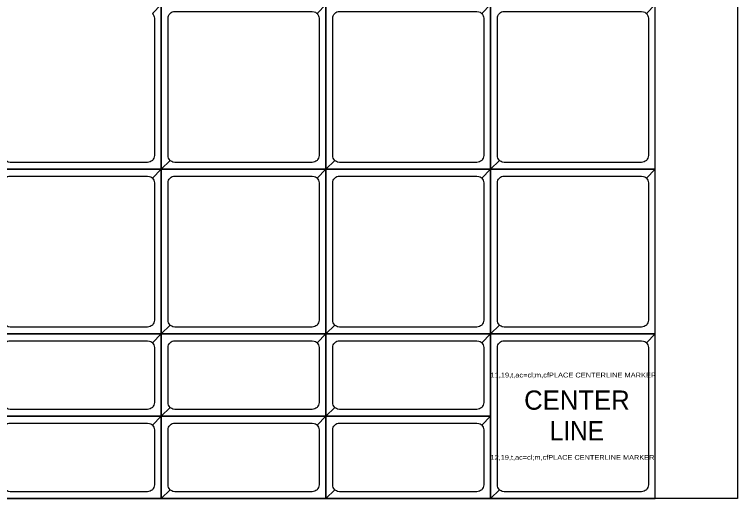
# Model space of a CAD drawing. Extents: x 67896 to 67908, y 49158.5 to 49162.6.
# Drawn here: x 67905.354 to 67907.989, y 49159.033 to 49160.797 of the extents above; entities that cross this region are included whole.
import ezdxf
from ezdxf.enums import TextEntityAlignment as Align

# ---------------------------------------------------------------- set-up
doc = ezdxf.new("R2010")
doc.units = 0
doc.header["$LTSCALE"] = 0.02
for name, color, linetype, lineweight in [('1', 7, 'Continuous', 25), ('2', 7, 'Continuous', 25), ('3', 7, 'Continuous', 25), ('4', 7, 'Continuous', 25), ('5', 7, 'Continuous', 25)]:
    doc.layers.add(name, color=color, linetype=linetype, lineweight=lineweight)
doc.layers.add('63', color=7, linetype='Continuous')

msp = doc.modelspace()

# ---------------------------------------------------------------- linework, layer by layer
at = {"layer": '1'}
for points in [[(67905.2889, 49160.2331), (67905.8889, 49160.2331), (67905.8889, 49160.8331), (67905.2889, 49160.8331)], [(67905.8889, 49160.2331), (67906.4889, 49160.2331), (67906.4889, 49160.8331), (67905.8889, 49160.8331)], [(67906.4889, 49160.2331), (67907.0889, 49160.2331), (67907.0889, 49160.8331), (67906.4889, 49160.8331)], [(67907.0889, 49160.2331), (67907.6889, 49160.2331), (67907.6889, 49160.8331), (67907.0889, 49160.8331)], [(67905.2889, 49159.6331), (67905.8889, 49159.6331), (67905.8889, 49160.2331), (67905.2889, 49160.2331)], [(67905.8889, 49159.6331), (67906.4889, 49159.6331), (67906.4889, 49160.2331), (67905.8889, 49160.2331)], [(67906.4889, 49159.6331), (67907.0889, 49159.6331), (67907.0889, 49160.2331), (67906.4889, 49160.2331)], [(67907.0889, 49159.6331), (67907.6889, 49159.6331), (67907.6889, 49160.2331), (67907.0889, 49160.2331)], [(67905.2889, 49159.3331), (67905.8889, 49159.3331), (67905.8889, 49159.6331), (67905.2889, 49159.6331)], [(67905.8889, 49159.3331), (67906.4889, 49159.3331), (67906.4889, 49159.6331), (67905.8889, 49159.6331)], [(67906.4889, 49159.3331), (67907.0889, 49159.3331), (67907.0889, 49159.6331), (67906.4889, 49159.6331)], [(67907.0889, 49159.0331), (67907.6889, 49159.0331), (67907.6889, 49159.6331), (67907.0889, 49159.6331)], [(67905.2889, 49159.0331), (67905.8889, 49159.0331), (67905.8889, 49159.3331), (67905.2889, 49159.3331)], [(67905.8889, 49159.0331), (67906.4889, 49159.0331), (67906.4889, 49159.3331), (67905.8889, 49159.3331)], [(67906.4889, 49159.0331), (67907.0889, 49159.0331), (67907.0889, 49159.3331), (67906.4889, 49159.3331)]]:
    msp.add_lwpolyline(points, close=True, dxfattribs=at)
at = {"layer": '2'}
for points in [[(67907.9889, 49159.0331), (67895.9889, 49159.0331), (67895.9889, 49162.6331), (67907.9889, 49162.6331)], [(67905.2889, 49160.2331), (67905.8889, 49160.2331), (67905.8889, 49160.8331), (67905.2889, 49160.8331)], [(67905.8889, 49160.2331), (67906.4889, 49160.2331), (67906.4889, 49160.8331), (67905.8889, 49160.8331)], [(67906.4889, 49160.2331), (67907.0889, 49160.2331), (67907.0889, 49160.8331), (67906.4889, 49160.8331)], [(67907.0889, 49160.2331), (67907.6889, 49160.2331), (67907.6889, 49160.8331), (67907.0889, 49160.8331)], [(67905.2889, 49159.6331), (67905.8889, 49159.6331), (67905.8889, 49160.2331), (67905.2889, 49160.2331)], [(67905.8889, 49159.6331), (67906.4889, 49159.6331), (67906.4889, 49160.2331), (67905.8889, 49160.2331)], [(67906.4889, 49159.6331), (67907.0889, 49159.6331), (67907.0889, 49160.2331), (67906.4889, 49160.2331)], [(67907.0889, 49159.6331), (67907.6889, 49159.6331), (67907.6889, 49160.2331), (67907.0889, 49160.2331)], [(67905.2889, 49159.3331), (67905.8889, 49159.3331), (67905.8889, 49159.6331), (67905.2889, 49159.6331)], [(67905.8889, 49159.3331), (67906.4889, 49159.3331), (67906.4889, 49159.6331), (67905.8889, 49159.6331)], [(67906.4889, 49159.3331), (67907.0889, 49159.3331), (67907.0889, 49159.6331), (67906.4889, 49159.6331)], [(67907.0889, 49159.0331), (67907.6889, 49159.0331), (67907.6889, 49159.6331), (67907.0889, 49159.6331)], [(67905.2889, 49159.0331), (67905.8889, 49159.0331), (67905.8889, 49159.3331), (67905.2889, 49159.3331)], [(67905.8889, 49159.0331), (67906.4889, 49159.0331), (67906.4889, 49159.3331), (67905.8889, 49159.3331)], [(67906.4889, 49159.0331), (67907.0889, 49159.0331), (67907.0889, 49159.3331), (67906.4889, 49159.3331)]]:
    msp.add_lwpolyline(points, close=True, dxfattribs=at)
at = {"layer": '3'}
for points in [[(67906.4889, 49160.8331), (67905.8889, 49160.8331), (67905.8889, 49160.2331), (67905.9212, 49160.2654), (67905.9181, 49160.2692), (67905.9158, 49160.2735), (67905.9144, 49160.2782), (67905.9139, 49160.2831), (67905.9139, 49160.7831), (67905.9144, 49160.788), (67905.9158, 49160.7927), (67905.9181, 49160.797), (67905.9212, 49160.8008), (67905.9212, 49160.8008), (67905.925, 49160.8039), (67905.9293, 49160.8062), (67905.934, 49160.8076), (67905.9389, 49160.8081), (67906.4389, 49160.8081), (67906.4462, 49160.807), (67906.4507, 49160.8051), (67906.4548, 49160.8024), (67906.4566, 49160.8008)], [(67907.0889, 49160.8331), (67906.4889, 49160.8331), (67906.4889, 49160.2331), (67906.5212, 49160.2654), (67906.5181, 49160.2692), (67906.5158, 49160.2735), (67906.5144, 49160.2782), (67906.5139, 49160.2831), (67906.5139, 49160.7831), (67906.5144, 49160.788), (67906.5158, 49160.7927), (67906.5181, 49160.797), (67906.5212, 49160.8008), (67906.5212, 49160.8008), (67906.525, 49160.8039), (67906.5293, 49160.8062), (67906.534, 49160.8076), (67906.5389, 49160.8081), (67907.0389, 49160.8081), (67907.0462, 49160.807), (67907.0507, 49160.8051), (67907.0548, 49160.8024), (67907.0566, 49160.8008)], [(67907.6889, 49160.8331), (67907.0889, 49160.8331), (67907.0889, 49160.2331), (67907.1212, 49160.2654), (67907.1181, 49160.2692), (67907.1158, 49160.2735), (67907.1144, 49160.2782), (67907.1139, 49160.2831), (67907.1139, 49160.7831), (67907.1144, 49160.788), (67907.1158, 49160.7927), (67907.1181, 49160.797), (67907.1212, 49160.8008), (67907.1212, 49160.8008), (67907.125, 49160.8039), (67907.1293, 49160.8062), (67907.134, 49160.8076), (67907.1389, 49160.8081), (67907.6389, 49160.8081), (67907.6462, 49160.807), (67907.6507, 49160.8051), (67907.6548, 49160.8024), (67907.6566, 49160.8008)], [(67905.8889, 49160.2331), (67905.2889, 49160.2331), (67905.2889, 49159.6331), (67905.3212, 49159.6654), (67905.3181, 49159.6692), (67905.3158, 49159.6735), (67905.3144, 49159.6782), (67905.3139, 49159.6831), (67905.3139, 49160.1831), (67905.3144, 49160.188), (67905.3158, 49160.1927), (67905.3181, 49160.197), (67905.3212, 49160.2008), (67905.3212, 49160.2008), (67905.325, 49160.2039), (67905.3293, 49160.2062), (67905.334, 49160.2076), (67905.3389, 49160.2081), (67905.8389, 49160.2081), (67905.8462, 49160.207), (67905.8507, 49160.2051), (67905.8548, 49160.2024), (67905.8566, 49160.2008)], [(67906.4889, 49160.2331), (67905.8889, 49160.2331), (67905.8889, 49159.6331), (67905.9212, 49159.6654), (67905.9181, 49159.6692), (67905.9158, 49159.6735), (67905.9144, 49159.6782), (67905.9139, 49159.6831), (67905.9139, 49160.1831), (67905.9144, 49160.188), (67905.9158, 49160.1927), (67905.9181, 49160.197), (67905.9212, 49160.2008), (67905.9212, 49160.2008), (67905.925, 49160.2039), (67905.9293, 49160.2062), (67905.934, 49160.2076), (67905.9389, 49160.2081), (67906.4389, 49160.2081), (67906.4462, 49160.207), (67906.4507, 49160.2051), (67906.4548, 49160.2024), (67906.4566, 49160.2008)], [(67907.0889, 49160.2331), (67906.4889, 49160.2331), (67906.4889, 49159.6331), (67906.5212, 49159.6654), (67906.5181, 49159.6692), (67906.5158, 49159.6735), (67906.5144, 49159.6782), (67906.5139, 49159.6831), (67906.5139, 49160.1831), (67906.5144, 49160.188), (67906.5158, 49160.1927), (67906.5181, 49160.197), (67906.5212, 49160.2008), (67906.5212, 49160.2008), (67906.525, 49160.2039), (67906.5293, 49160.2062), (67906.534, 49160.2076), (67906.5389, 49160.2081), (67907.0389, 49160.2081), (67907.0462, 49160.207), (67907.0507, 49160.2051), (67907.0548, 49160.2024), (67907.0566, 49160.2008)], [(67907.6889, 49160.2331), (67907.0889, 49160.2331), (67907.0889, 49159.6331), (67907.1212, 49159.6654), (67907.1181, 49159.6692), (67907.1158, 49159.6735), (67907.1144, 49159.6782), (67907.1139, 49159.6831), (67907.1139, 49160.1831), (67907.1144, 49160.188), (67907.1158, 49160.1927), (67907.1181, 49160.197), (67907.1212, 49160.2008), (67907.1212, 49160.2008), (67907.125, 49160.2039), (67907.1293, 49160.2062), (67907.134, 49160.2076), (67907.1389, 49160.2081), (67907.6389, 49160.2081), (67907.6462, 49160.207), (67907.6507, 49160.2051), (67907.6548, 49160.2024), (67907.6566, 49160.2008)], [(67905.8889, 49159.6331), (67905.2889, 49159.6331), (67905.2889, 49159.3331), (67905.3212, 49159.3654), (67905.3181, 49159.3692), (67905.3158, 49159.3735), (67905.3144, 49159.3782), (67905.3139, 49159.3831), (67905.3139, 49159.5831), (67905.3144, 49159.588), (67905.3158, 49159.5927), (67905.3181, 49159.597), (67905.3212, 49159.6008), (67905.3212, 49159.6008), (67905.325, 49159.6039), (67905.3293, 49159.6062), (67905.334, 49159.6076), (67905.3389, 49159.6081), (67905.8389, 49159.6081), (67905.8462, 49159.607), (67905.8507, 49159.6051), (67905.8548, 49159.6024), (67905.8566, 49159.6008)], [(67906.4889, 49159.6331), (67905.8889, 49159.6331), (67905.8889, 49159.3331), (67905.9212, 49159.3654), (67905.9181, 49159.3692), (67905.9158, 49159.3735), (67905.9144, 49159.3782), (67905.9139, 49159.3831), (67905.9139, 49159.5831), (67905.9144, 49159.588), (67905.9158, 49159.5927), (67905.9181, 49159.597), (67905.9212, 49159.6008), (67905.9212, 49159.6008), (67905.925, 49159.6039), (67905.9293, 49159.6062), (67905.934, 49159.6076), (67905.9389, 49159.6081), (67906.4389, 49159.6081), (67906.4462, 49159.607), (67906.4507, 49159.6051), (67906.4548, 49159.6024), (67906.4566, 49159.6008)], [(67907.0889, 49159.6331), (67906.4889, 49159.6331), (67906.4889, 49159.3331), (67906.5212, 49159.3654), (67906.5181, 49159.3692), (67906.5158, 49159.3735), (67906.5144, 49159.3782), (67906.5139, 49159.3831), (67906.5139, 49159.5831), (67906.5144, 49159.588), (67906.5158, 49159.5927), (67906.5181, 49159.597), (67906.5212, 49159.6008), (67906.5212, 49159.6008), (67906.525, 49159.6039), (67906.5293, 49159.6062), (67906.534, 49159.6076), (67906.5389, 49159.6081), (67907.0389, 49159.6081), (67907.0462, 49159.607), (67907.0507, 49159.6051), (67907.0548, 49159.6024), (67907.0566, 49159.6008)], [(67907.6889, 49159.6331), (67907.0889, 49159.6331), (67907.0889, 49159.0331), (67907.1212, 49159.0654), (67907.1181, 49159.0692), (67907.1158, 49159.0735), (67907.1144, 49159.0782), (67907.1139, 49159.0831), (67907.1139, 49159.5831), (67907.1144, 49159.588), (67907.1158, 49159.5927), (67907.1181, 49159.597), (67907.1212, 49159.6008), (67907.1212, 49159.6008), (67907.125, 49159.6039), (67907.1293, 49159.6062), (67907.134, 49159.6076), (67907.1389, 49159.6081), (67907.6389, 49159.6081), (67907.6462, 49159.607), (67907.6507, 49159.6051), (67907.6548, 49159.6024), (67907.6566, 49159.6008)], [(67905.8889, 49159.3331), (67905.2889, 49159.3331), (67905.2889, 49159.0331), (67905.3212, 49159.0654), (67905.3181, 49159.0692), (67905.3158, 49159.0735), (67905.3144, 49159.0782), (67905.3139, 49159.0831), (67905.3139, 49159.2831), (67905.3144, 49159.288), (67905.3158, 49159.2927), (67905.3181, 49159.297), (67905.3212, 49159.3008), (67905.3212, 49159.3008), (67905.325, 49159.3039), (67905.3293, 49159.3062), (67905.334, 49159.3076), (67905.3389, 49159.3081), (67905.8389, 49159.3081), (67905.8462, 49159.307), (67905.8507, 49159.3051), (67905.8548, 49159.3024), (67905.8566, 49159.3008)], [(67906.4889, 49159.3331), (67905.8889, 49159.3331), (67905.8889, 49159.0331), (67905.9212, 49159.0654), (67905.9181, 49159.0692), (67905.9158, 49159.0735), (67905.9144, 49159.0782), (67905.9139, 49159.0831), (67905.9139, 49159.2831), (67905.9144, 49159.288), (67905.9158, 49159.2927), (67905.9181, 49159.297), (67905.9212, 49159.3008), (67905.9212, 49159.3008), (67905.925, 49159.3039), (67905.9293, 49159.3062), (67905.934, 49159.3076), (67905.9389, 49159.3081), (67906.4389, 49159.3081), (67906.4462, 49159.307), (67906.4507, 49159.3051), (67906.4548, 49159.3024), (67906.4566, 49159.3008)], [(67907.0889, 49159.3331), (67906.4889, 49159.3331), (67906.4889, 49159.0331), (67906.5212, 49159.0654), (67906.5181, 49159.0692), (67906.5158, 49159.0735), (67906.5144, 49159.0782), (67906.5139, 49159.0831), (67906.5139, 49159.2831), (67906.5144, 49159.288), (67906.5158, 49159.2927), (67906.5181, 49159.297), (67906.5212, 49159.3008), (67906.5212, 49159.3008), (67906.525, 49159.3039), (67906.5293, 49159.3062), (67906.534, 49159.3076), (67906.5389, 49159.3081), (67907.0389, 49159.3081), (67907.0462, 49159.307), (67907.0507, 49159.3051), (67907.0548, 49159.3024), (67907.0566, 49159.3008)]]:
    msp.add_lwpolyline(points, close=True, dxfattribs=at)
at = {"layer": '4'}
for points in [[(67905.2889, 49160.2331), (67905.8889, 49160.2331), (67905.8889, 49160.8331), (67905.8566, 49160.8008), (67905.8597, 49160.797), (67905.862, 49160.7927), (67905.8634, 49160.788), (67905.8639, 49160.7831), (67905.8639, 49160.2831), (67905.8634, 49160.2782), (67905.862, 49160.2735), (67905.8597, 49160.2692), (67905.8566, 49160.2654), (67905.8566, 49160.2654), (67905.8528, 49160.2623), (67905.8485, 49160.26), (67905.8438, 49160.2586), (67905.8389, 49160.2581), (67905.3389, 49160.2581), (67905.3316, 49160.2592), (67905.3271, 49160.2611), (67905.323, 49160.2638), (67905.3212, 49160.2654)], [(67905.8889, 49160.2331), (67906.4889, 49160.2331), (67906.4889, 49160.8331), (67906.4566, 49160.8008), (67906.4597, 49160.797), (67906.462, 49160.7927), (67906.4634, 49160.788), (67906.4639, 49160.7831), (67906.4639, 49160.2831), (67906.4634, 49160.2782), (67906.462, 49160.2735), (67906.4597, 49160.2692), (67906.4566, 49160.2654), (67906.4566, 49160.2654), (67906.4528, 49160.2623), (67906.4485, 49160.26), (67906.4438, 49160.2586), (67906.4389, 49160.2581), (67905.9389, 49160.2581), (67905.9316, 49160.2592), (67905.9271, 49160.2611), (67905.923, 49160.2638), (67905.9212, 49160.2654)], [(67906.4889, 49160.2331), (67907.0889, 49160.2331), (67907.0889, 49160.8331), (67907.0566, 49160.8008), (67907.0597, 49160.797), (67907.062, 49160.7927), (67907.0634, 49160.788), (67907.0639, 49160.7831), (67907.0639, 49160.2831), (67907.0634, 49160.2782), (67907.062, 49160.2735), (67907.0597, 49160.2692), (67907.0566, 49160.2654), (67907.0566, 49160.2654), (67907.0528, 49160.2623), (67907.0485, 49160.26), (67907.0438, 49160.2586), (67907.0389, 49160.2581), (67906.5389, 49160.2581), (67906.5316, 49160.2592), (67906.5271, 49160.2611), (67906.523, 49160.2638), (67906.5212, 49160.2654)], [(67907.0889, 49160.2331), (67907.6889, 49160.2331), (67907.6889, 49160.8331), (67907.6566, 49160.8008), (67907.6597, 49160.797), (67907.662, 49160.7927), (67907.6634, 49160.788), (67907.6639, 49160.7831), (67907.6639, 49160.2831), (67907.6634, 49160.2782), (67907.662, 49160.2735), (67907.6597, 49160.2692), (67907.6566, 49160.2654), (67907.6566, 49160.2654), (67907.6528, 49160.2623), (67907.6485, 49160.26), (67907.6438, 49160.2586), (67907.6389, 49160.2581), (67907.1389, 49160.2581), (67907.1316, 49160.2592), (67907.1271, 49160.2611), (67907.123, 49160.2638), (67907.1212, 49160.2654)], [(67905.2889, 49159.6331), (67905.8889, 49159.6331), (67905.8889, 49160.2331), (67905.8566, 49160.2008), (67905.8597, 49160.197), (67905.862, 49160.1927), (67905.8634, 49160.188), (67905.8639, 49160.1831), (67905.8639, 49159.6831), (67905.8634, 49159.6782), (67905.862, 49159.6735), (67905.8597, 49159.6692), (67905.8566, 49159.6654), (67905.8566, 49159.6654), (67905.8528, 49159.6623), (67905.8485, 49159.66), (67905.8438, 49159.6586), (67905.8389, 49159.6581), (67905.3389, 49159.6581), (67905.3316, 49159.6592), (67905.3271, 49159.6611), (67905.323, 49159.6638), (67905.3212, 49159.6654)], [(67905.8889, 49159.6331), (67906.4889, 49159.6331), (67906.4889, 49160.2331), (67906.4566, 49160.2008), (67906.4597, 49160.197), (67906.462, 49160.1927), (67906.4634, 49160.188), (67906.4639, 49160.1831), (67906.4639, 49159.6831), (67906.4634, 49159.6782), (67906.462, 49159.6735), (67906.4597, 49159.6692), (67906.4566, 49159.6654), (67906.4566, 49159.6654), (67906.4528, 49159.6623), (67906.4485, 49159.66), (67906.4438, 49159.6586), (67906.4389, 49159.6581), (67905.9389, 49159.6581), (67905.9316, 49159.6592), (67905.9271, 49159.6611), (67905.923, 49159.6638), (67905.9212, 49159.6654)], [(67906.4889, 49159.6331), (67907.0889, 49159.6331), (67907.0889, 49160.2331), (67907.0566, 49160.2008), (67907.0597, 49160.197), (67907.062, 49160.1927), (67907.0634, 49160.188), (67907.0639, 49160.1831), (67907.0639, 49159.6831), (67907.0634, 49159.6782), (67907.062, 49159.6735), (67907.0597, 49159.6692), (67907.0566, 49159.6654), (67907.0566, 49159.6654), (67907.0528, 49159.6623), (67907.0485, 49159.66), (67907.0438, 49159.6586), (67907.0389, 49159.6581), (67906.5389, 49159.6581), (67906.5316, 49159.6592), (67906.5271, 49159.6611), (67906.523, 49159.6638), (67906.5212, 49159.6654)], [(67907.0889, 49159.6331), (67907.6889, 49159.6331), (67907.6889, 49160.2331), (67907.6566, 49160.2008), (67907.6597, 49160.197), (67907.662, 49160.1927), (67907.6634, 49160.188), (67907.6639, 49160.1831), (67907.6639, 49159.6831), (67907.6634, 49159.6782), (67907.662, 49159.6735), (67907.6597, 49159.6692), (67907.6566, 49159.6654), (67907.6566, 49159.6654), (67907.6528, 49159.6623), (67907.6485, 49159.66), (67907.6438, 49159.6586), (67907.6389, 49159.6581), (67907.1389, 49159.6581), (67907.1316, 49159.6592), (67907.1271, 49159.6611), (67907.123, 49159.6638), (67907.1212, 49159.6654)], [(67905.2889, 49159.3331), (67905.8889, 49159.3331), (67905.8889, 49159.6331), (67905.8566, 49159.6008), (67905.8597, 49159.597), (67905.862, 49159.5927), (67905.8634, 49159.588), (67905.8639, 49159.5831), (67905.8639, 49159.3831), (67905.8634, 49159.3782), (67905.862, 49159.3735), (67905.8597, 49159.3692), (67905.8566, 49159.3654), (67905.8566, 49159.3654), (67905.8528, 49159.3623), (67905.8485, 49159.36), (67905.8438, 49159.3586), (67905.8389, 49159.3581), (67905.3389, 49159.3581), (67905.3316, 49159.3592), (67905.3271, 49159.3611), (67905.323, 49159.3638), (67905.3212, 49159.3654)], [(67905.8889, 49159.3331), (67906.4889, 49159.3331), (67906.4889, 49159.6331), (67906.4566, 49159.6008), (67906.4597, 49159.597), (67906.462, 49159.5927), (67906.4634, 49159.588), (67906.4639, 49159.5831), (67906.4639, 49159.3831), (67906.4634, 49159.3782), (67906.462, 49159.3735), (67906.4597, 49159.3692), (67906.4566, 49159.3654), (67906.4566, 49159.3654), (67906.4528, 49159.3623), (67906.4485, 49159.36), (67906.4438, 49159.3586), (67906.4389, 49159.3581), (67905.9389, 49159.3581), (67905.9316, 49159.3592), (67905.9271, 49159.3611), (67905.923, 49159.3638), (67905.9212, 49159.3654)], [(67906.4889, 49159.3331), (67907.0889, 49159.3331), (67907.0889, 49159.6331), (67907.0566, 49159.6008), (67907.0597, 49159.597), (67907.062, 49159.5927), (67907.0634, 49159.588), (67907.0639, 49159.5831), (67907.0639, 49159.3831), (67907.0634, 49159.3782), (67907.062, 49159.3735), (67907.0597, 49159.3692), (67907.0566, 49159.3654), (67907.0566, 49159.3654), (67907.0528, 49159.3623), (67907.0485, 49159.36), (67907.0438, 49159.3586), (67907.0389, 49159.3581), (67906.5389, 49159.3581), (67906.5316, 49159.3592), (67906.5271, 49159.3611), (67906.523, 49159.3638), (67906.5212, 49159.3654)], [(67907.0889, 49159.0331), (67907.6889, 49159.0331), (67907.6889, 49159.6331), (67907.6566, 49159.6008), (67907.6597, 49159.597), (67907.662, 49159.5927), (67907.6634, 49159.588), (67907.6639, 49159.5831), (67907.6639, 49159.0831), (67907.6634, 49159.0782), (67907.662, 49159.0735), (67907.6597, 49159.0692), (67907.6566, 49159.0654), (67907.6566, 49159.0654), (67907.6528, 49159.0623), (67907.6485, 49159.06), (67907.6438, 49159.0586), (67907.6389, 49159.0581), (67907.1389, 49159.0581), (67907.1316, 49159.0592), (67907.1271, 49159.0611), (67907.123, 49159.0638), (67907.1212, 49159.0654)], [(67905.2889, 49159.0331), (67905.8889, 49159.0331), (67905.8889, 49159.3331), (67905.8566, 49159.3008), (67905.8597, 49159.297), (67905.862, 49159.2927), (67905.8634, 49159.288), (67905.8639, 49159.2831), (67905.8639, 49159.0831), (67905.8634, 49159.0782), (67905.862, 49159.0735), (67905.8597, 49159.0692), (67905.8566, 49159.0654), (67905.8566, 49159.0654), (67905.8528, 49159.0623), (67905.8485, 49159.06), (67905.8438, 49159.0586), (67905.8389, 49159.0581), (67905.3389, 49159.0581), (67905.3316, 49159.0592), (67905.3271, 49159.0611), (67905.323, 49159.0638), (67905.3212, 49159.0654)], [(67905.8889, 49159.0331), (67906.4889, 49159.0331), (67906.4889, 49159.3331), (67906.4566, 49159.3008), (67906.4597, 49159.297), (67906.462, 49159.2927), (67906.4634, 49159.288), (67906.4639, 49159.2831), (67906.4639, 49159.0831), (67906.4634, 49159.0782), (67906.462, 49159.0735), (67906.4597, 49159.0692), (67906.4566, 49159.0654), (67906.4566, 49159.0654), (67906.4528, 49159.0623), (67906.4485, 49159.06), (67906.4438, 49159.0586), (67906.4389, 49159.0581), (67905.9389, 49159.0581), (67905.9316, 49159.0592), (67905.9271, 49159.0611), (67905.923, 49159.0638), (67905.9212, 49159.0654)], [(67906.4889, 49159.0331), (67907.0889, 49159.0331), (67907.0889, 49159.3331), (67907.0566, 49159.3008), (67907.0597, 49159.297), (67907.062, 49159.2927), (67907.0634, 49159.288), (67907.0639, 49159.2831), (67907.0639, 49159.0831), (67907.0634, 49159.0782), (67907.062, 49159.0735), (67907.0597, 49159.0692), (67907.0566, 49159.0654), (67907.0566, 49159.0654), (67907.0528, 49159.0623), (67907.0485, 49159.06), (67907.0438, 49159.0586), (67907.0389, 49159.0581), (67906.5389, 49159.0581), (67906.5316, 49159.0592), (67906.5271, 49159.0611), (67906.523, 49159.0638), (67906.5212, 49159.0654)]]:
    msp.add_lwpolyline(points, close=True, dxfattribs=at)

# ---------------------------------------------------------------- texts
at = {"layer": '5'}
msp.add_text('CENTER', height=0.07, dxfattribs=at).set_placement((67907.4037, 49159.3568), align=Align.CENTER)
at = {"layer": '5', "width": 0.95}
msp.add_text('LINE', height=0.07, dxfattribs=at).set_placement((67907.4036, 49159.2452), align=Align.CENTER)
at = {"layer": '63', "width": 1.15}
for s, height, p in [('11,19,t,ac=cl;m,cfPLACE CENTERLINE MARKER', 0.0176, (67907.0889, 49159.4743)), ('12,19,t,ac=cl;m,cfPLACE CENTERLINE MARKER', 0.0174, (67907.0889, 49159.1744))]:
    msp.add_text(s, height=height, dxfattribs=at).set_placement(p)

doc.saveas('drawing.dxf')
